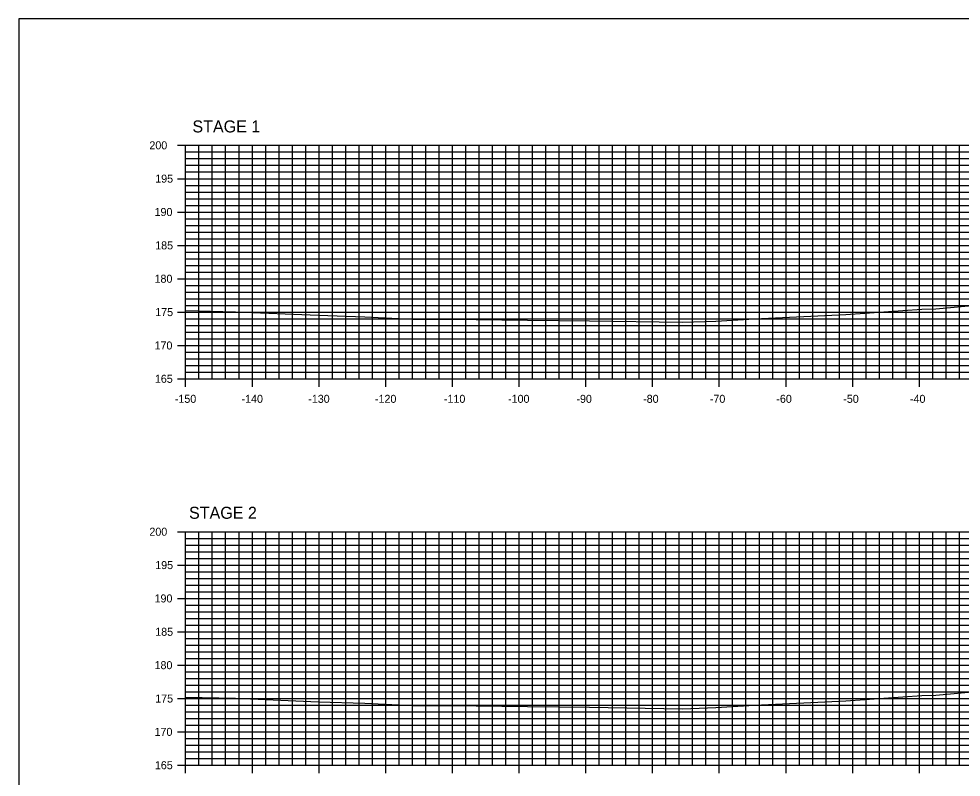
# Model space of a CAD drawing. Extents: x 1405440 to 1409538, y 1842123 to 1843178.
# Drawn here: x 1408707.6 to 1408848.9, y 1842829.8 to 1842943.5 of the extents above; entities that cross this region are included whole.
import ezdxf

# ---------------------------------------------------------------- set-up
doc = ezdxf.new("R2010")
doc.units = 0
for name, color, linetype in [('R_Axis', 7, 'Continuous'), ('R_Axis Annot', 7, 'Continuous'), ('R_Exist Surface', 7, 'Continuous'), ('R_Grid_Minor', 7, 'Continuous'), ('R_Grid_Sta', 7, 'Continuous'), ('R_Grid_Tick', 7, 'Continuous')]:
    doc.layers.add(name, color=color, linetype=linetype)

msp = doc.modelspace()

# ---------------------------------------------------------------- linework, layer by layer
for p, q in [((1408732.62, 1842924.51), (1409032.62, 1842924.51)), ((1408732.62, 1842889.51), (1408732.62, 1842924.51)), ((1408742.62, 1842889.51), (1408742.62, 1842924.51)), ((1408752.62, 1842889.51), (1408752.62, 1842924.51)), ((1408762.62, 1842889.51), (1408762.62, 1842924.51)), ((1408772.62, 1842889.51), (1408772.62, 1842924.51)), ((1408782.62, 1842889.51), (1408782.62, 1842924.51)), ((1408792.62, 1842889.51), (1408792.62, 1842924.51)), ((1408802.62, 1842889.51), (1408802.62, 1842924.51)), ((1408812.62, 1842889.51), (1408812.62, 1842924.51)), ((1408822.62, 1842889.51), (1408822.62, 1842924.51)), ((1408832.62, 1842889.51), (1408832.62, 1842924.51)), ((1408842.62, 1842889.51), (1408842.62, 1842924.51)), ((1408732.62, 1842919.51), (1409032.62, 1842919.51)), ((1408732.62, 1842914.51), (1409032.62, 1842914.51)), ((1408732.62, 1842909.51), (1409032.62, 1842909.51)), ((1408732.62, 1842904.51), (1409032.62, 1842904.51)), ((1408732.62, 1842899.51), (1409032.62, 1842899.51)), ((1408732.62, 1842894.51), (1409032.62, 1842894.51)), ((1408732.62, 1842889.51), (1409032.62, 1842889.51)), ((1408732.62, 1842889.51), (1409032.62, 1842889.51)), ((1408732.62, 1842866.59), (1409032.62, 1842866.59)), ((1408732.62, 1842831.59), (1408732.62, 1842866.59)), ((1408742.62, 1842831.59), (1408742.62, 1842866.59)), ((1408752.62, 1842831.59), (1408752.62, 1842866.59)), ((1408762.62, 1842831.59), (1408762.62, 1842866.59)), ((1408772.62, 1842831.59), (1408772.62, 1842866.59)), ((1408782.62, 1842831.59), (1408782.62, 1842866.59)), ((1408792.62, 1842831.59), (1408792.62, 1842866.59)), ((1408802.62, 1842831.59), (1408802.62, 1842866.59)), ((1408812.62, 1842831.59), (1408812.62, 1842866.59)), ((1408822.62, 1842831.59), (1408822.62, 1842866.59)), ((1408832.62, 1842831.59), (1408832.62, 1842866.59)), ((1408842.62, 1842831.59), (1408842.62, 1842866.59)), ((1408732.62, 1842861.59), (1409032.62, 1842861.59)), ((1408732.62, 1842856.59), (1409032.62, 1842856.59)), ((1408732.62, 1842851.59), (1409032.62, 1842851.59)), ((1408732.62, 1842846.59), (1409032.62, 1842846.59)), ((1408732.62, 1842841.59), (1409032.62, 1842841.59)), ((1408732.62, 1842836.59), (1409032.62, 1842836.59)), ((1408732.62, 1842831.59), (1409032.62, 1842831.59)), ((1408732.62, 1842831.59), (1409032.62, 1842831.59))]:
    msp.add_line(p, q)
msp.add_lwpolyline([(1408707.62, 1842723.47), (1409047.62, 1842723.47), (1409047.62, 1842943.47), (1408707.62, 1842943.47)], close=True)
at = {"layer": 'R_Axis'}
for p, q in [((1408732.62, 1842889.51), (1408732.62, 1842924.51)), ((1408732.62, 1842831.59), (1408732.62, 1842866.59))]:
    msp.add_line(p, q, dxfattribs=at)
at = {"layer": 'R_Exist Surface'}
for points in [[(1408732.62, 1842899.73), (1408740.12, 1842899.55), (1408752.53, 1842899.03), (1408759.46, 1842898.81), (1408766.51, 1842898.45), (1408776.19, 1842898.39), (1408783.89, 1842898.29), (1408793.18, 1842898.22), (1408807.12, 1842897.98), (1408812.08, 1842898.16), (1408817.89, 1842898.49), (1408831.59, 1842899.15), (1408842.97, 1842899.94), (1408842.98, 1842899.94), (1408845.09, 1842900.01), (1408851.63, 1842900.62)], [(1408732.62, 1842841.81), (1408740.12, 1842841.63), (1408752.53, 1842841.11), (1408759.46, 1842840.89), (1408766.51, 1842840.53), (1408776.19, 1842840.47), (1408783.89, 1842840.37), (1408793.18, 1842840.3), (1408807.12, 1842840.06), (1408812.08, 1842840.24), (1408817.89, 1842840.57), (1408831.59, 1842841.23), (1408842.97, 1842842.02), (1408842.98, 1842842.02), (1408845.09, 1842842.1), (1408851.63, 1842842.71)]]:
    msp.add_lwpolyline(points, dxfattribs=at)
at = {"layer": 'R_Grid_Minor'}
for p, q in [((1408732.62, 1842889.51), (1408732.62, 1842924.51)), ((1408734.62, 1842889.51), (1408734.62, 1842924.51)), ((1408736.62, 1842889.51), (1408736.62, 1842924.51)), ((1408738.62, 1842889.51), (1408738.62, 1842924.51)), ((1408740.62, 1842889.51), (1408740.62, 1842924.51)), ((1408744.62, 1842889.51), (1408744.62, 1842924.51)), ((1408746.62, 1842889.51), (1408746.62, 1842924.51)), ((1408748.62, 1842889.51), (1408748.62, 1842924.51)), ((1408750.62, 1842889.51), (1408750.62, 1842924.51)), ((1408754.62, 1842889.51), (1408754.62, 1842924.51)), ((1408756.62, 1842889.51), (1408756.62, 1842924.51)), ((1408758.62, 1842889.51), (1408758.62, 1842924.51)), ((1408760.62, 1842889.51), (1408760.62, 1842924.51)), ((1408764.62, 1842889.51), (1408764.62, 1842924.51)), ((1408766.62, 1842889.51), (1408766.62, 1842924.51)), ((1408768.62, 1842889.51), (1408768.62, 1842924.51)), ((1408770.62, 1842889.51), (1408770.62, 1842924.51)), ((1408774.62, 1842889.51), (1408774.62, 1842924.51)), ((1408776.62, 1842889.51), (1408776.62, 1842924.51)), ((1408778.62, 1842889.51), (1408778.62, 1842924.51)), ((1408780.62, 1842889.51), (1408780.62, 1842924.51)), ((1408784.62, 1842889.51), (1408784.62, 1842924.51)), ((1408786.62, 1842889.51), (1408786.62, 1842924.51)), ((1408788.62, 1842889.51), (1408788.62, 1842924.51)), ((1408790.62, 1842889.51), (1408790.62, 1842924.51)), ((1408794.62, 1842889.51), (1408794.62, 1842924.51)), ((1408796.62, 1842889.51), (1408796.62, 1842924.51)), ((1408798.62, 1842889.51), (1408798.62, 1842924.51)), ((1408800.62, 1842889.51), (1408800.62, 1842924.51)), ((1408804.62, 1842889.51), (1408804.62, 1842924.51)), ((1408806.62, 1842889.51), (1408806.62, 1842924.51)), ((1408808.62, 1842889.51), (1408808.62, 1842924.51)), ((1408810.62, 1842889.51), (1408810.62, 1842924.51)), ((1408814.62, 1842889.51), (1408814.62, 1842924.51)), ((1408816.62, 1842889.51), (1408816.62, 1842924.51)), ((1408818.62, 1842889.51), (1408818.62, 1842924.51)), ((1408820.62, 1842889.51), (1408820.62, 1842924.51)), ((1408824.62, 1842889.51), (1408824.62, 1842924.51)), ((1408826.62, 1842889.51), (1408826.62, 1842924.51)), ((1408828.62, 1842889.51), (1408828.62, 1842924.51)), ((1408830.62, 1842889.51), (1408830.62, 1842924.51)), ((1408834.62, 1842889.51), (1408834.62, 1842924.51)), ((1408836.62, 1842889.51), (1408836.62, 1842924.51)), ((1408838.62, 1842889.51), (1408838.62, 1842924.51)), ((1408840.62, 1842889.51), (1408840.62, 1842924.51)), ((1408844.62, 1842889.51), (1408844.62, 1842924.51)), ((1408846.62, 1842889.51), (1408846.62, 1842924.51)), ((1408848.62, 1842889.51), (1408848.62, 1842924.51)), ((1408732.62, 1842923.51), (1409032.62, 1842923.51)), ((1408732.62, 1842922.51), (1409032.62, 1842922.51)), ((1408732.62, 1842921.51), (1409032.62, 1842921.51)), ((1408732.62, 1842920.51), (1409032.62, 1842920.51)), ((1408732.62, 1842918.51), (1409032.62, 1842918.51)), ((1408732.62, 1842917.51), (1409032.62, 1842917.51)), ((1408732.62, 1842916.51), (1409032.62, 1842916.51)), ((1408732.62, 1842915.51), (1409032.62, 1842915.51)), ((1408732.62, 1842913.51), (1409032.62, 1842913.51)), ((1408732.62, 1842912.51), (1409032.62, 1842912.51)), ((1408732.62, 1842911.51), (1409032.62, 1842911.51)), ((1408732.62, 1842910.51), (1409032.62, 1842910.51)), ((1408732.62, 1842908.51), (1409032.62, 1842908.51)), ((1408732.62, 1842907.51), (1409032.62, 1842907.51)), ((1408732.62, 1842906.51), (1409032.62, 1842906.51)), ((1408732.62, 1842905.51), (1409032.62, 1842905.51)), ((1408732.62, 1842903.51), (1409032.62, 1842903.51)), ((1408732.62, 1842902.51), (1409032.62, 1842902.51)), ((1408732.62, 1842901.51), (1409032.62, 1842901.51)), ((1408732.62, 1842900.51), (1409032.62, 1842900.51)), ((1408732.62, 1842898.51), (1409032.62, 1842898.51)), ((1408732.62, 1842897.51), (1409032.62, 1842897.51)), ((1408732.62, 1842896.51), (1409032.62, 1842896.51)), ((1408732.62, 1842895.51), (1409032.62, 1842895.51)), ((1408732.62, 1842893.51), (1409032.62, 1842893.51)), ((1408732.62, 1842892.51), (1409032.62, 1842892.51)), ((1408732.62, 1842891.51), (1409032.62, 1842891.51)), ((1408732.62, 1842890.51), (1409032.62, 1842890.51)), ((1408732.62, 1842831.59), (1408732.62, 1842866.59)), ((1408734.62, 1842831.59), (1408734.62, 1842866.59)), ((1408736.62, 1842831.59), (1408736.62, 1842866.59)), ((1408738.62, 1842831.59), (1408738.62, 1842866.59)), ((1408740.62, 1842831.59), (1408740.62, 1842866.59)), ((1408744.62, 1842831.59), (1408744.62, 1842866.59)), ((1408746.62, 1842831.59), (1408746.62, 1842866.59)), ((1408748.62, 1842831.59), (1408748.62, 1842866.59)), ((1408750.62, 1842831.59), (1408750.62, 1842866.59)), ((1408754.62, 1842831.59), (1408754.62, 1842866.59)), ((1408756.62, 1842831.59), (1408756.62, 1842866.59)), ((1408758.62, 1842831.59), (1408758.62, 1842866.59)), ((1408760.62, 1842831.59), (1408760.62, 1842866.59)), ((1408764.62, 1842831.59), (1408764.62, 1842866.59)), ((1408766.62, 1842831.59), (1408766.62, 1842866.59)), ((1408768.62, 1842831.59), (1408768.62, 1842866.59)), ((1408770.62, 1842831.59), (1408770.62, 1842866.59)), ((1408774.62, 1842831.59), (1408774.62, 1842866.59)), ((1408776.62, 1842831.59), (1408776.62, 1842866.59)), ((1408778.62, 1842831.59), (1408778.62, 1842866.59)), ((1408780.62, 1842831.59), (1408780.62, 1842866.59)), ((1408784.62, 1842831.59), (1408784.62, 1842866.59)), ((1408786.62, 1842831.59), (1408786.62, 1842866.59)), ((1408788.62, 1842831.59), (1408788.62, 1842866.59)), ((1408790.62, 1842831.59), (1408790.62, 1842866.59)), ((1408794.62, 1842831.59), (1408794.62, 1842866.59)), ((1408796.62, 1842831.59), (1408796.62, 1842866.59)), ((1408798.62, 1842831.59), (1408798.62, 1842866.59)), ((1408800.62, 1842831.59), (1408800.62, 1842866.59)), ((1408804.62, 1842831.59), (1408804.62, 1842866.59)), ((1408806.62, 1842831.59), (1408806.62, 1842866.59)), ((1408808.62, 1842831.59), (1408808.62, 1842866.59)), ((1408810.62, 1842831.59), (1408810.62, 1842866.59)), ((1408814.62, 1842831.59), (1408814.62, 1842866.59)), ((1408816.62, 1842831.59), (1408816.62, 1842866.59)), ((1408818.62, 1842831.59), (1408818.62, 1842866.59)), ((1408820.62, 1842831.59), (1408820.62, 1842866.59)), ((1408824.62, 1842831.59), (1408824.62, 1842866.59)), ((1408826.62, 1842831.59), (1408826.62, 1842866.59)), ((1408828.62, 1842831.59), (1408828.62, 1842866.59)), ((1408830.62, 1842831.59), (1408830.62, 1842866.59)), ((1408834.62, 1842831.59), (1408834.62, 1842866.59)), ((1408836.62, 1842831.59), (1408836.62, 1842866.59)), ((1408838.62, 1842831.59), (1408838.62, 1842866.59)), ((1408840.62, 1842831.59), (1408840.62, 1842866.59)), ((1408844.62, 1842831.59), (1408844.62, 1842866.59)), ((1408846.62, 1842831.59), (1408846.62, 1842866.59)), ((1408848.62, 1842831.59), (1408848.62, 1842866.59)), ((1408732.62, 1842865.59), (1409032.62, 1842865.59)), ((1408732.62, 1842864.59), (1409032.62, 1842864.59)), ((1408732.62, 1842863.59), (1409032.62, 1842863.59)), ((1408732.62, 1842862.59), (1409032.62, 1842862.59)), ((1408732.62, 1842860.59), (1409032.62, 1842860.59)), ((1408732.62, 1842859.59), (1409032.62, 1842859.59)), ((1408732.62, 1842858.59), (1409032.62, 1842858.59)), ((1408732.62, 1842857.59), (1409032.62, 1842857.59)), ((1408732.62, 1842855.59), (1409032.62, 1842855.59)), ((1408732.62, 1842854.59), (1409032.62, 1842854.59)), ((1408732.62, 1842853.59), (1409032.62, 1842853.59)), ((1408732.62, 1842852.59), (1409032.62, 1842852.59)), ((1408732.62, 1842850.59), (1409032.62, 1842850.59)), ((1408732.62, 1842849.59), (1409032.62, 1842849.59)), ((1408732.62, 1842848.59), (1409032.62, 1842848.59)), ((1408732.62, 1842847.59), (1409032.62, 1842847.59)), ((1408732.62, 1842845.59), (1409032.62, 1842845.59)), ((1408732.62, 1842844.59), (1409032.62, 1842844.59)), ((1408732.62, 1842843.59), (1409032.62, 1842843.59)), ((1408732.62, 1842842.59), (1409032.62, 1842842.59)), ((1408732.62, 1842840.59), (1409032.62, 1842840.59)), ((1408732.62, 1842839.59), (1409032.62, 1842839.59)), ((1408732.62, 1842838.59), (1409032.62, 1842838.59)), ((1408732.62, 1842837.59), (1409032.62, 1842837.59)), ((1408732.62, 1842835.59), (1409032.62, 1842835.59)), ((1408732.62, 1842834.59), (1409032.62, 1842834.59)), ((1408732.62, 1842833.59), (1409032.62, 1842833.59)), ((1408732.62, 1842832.59), (1409032.62, 1842832.59))]:
    msp.add_line(p, q, dxfattribs=at)
at = {"layer": 'R_Grid_Tick'}
for p, q in [((1408731.42, 1842924.51), (1408733.82, 1842924.51)), ((1408732.62, 1842923.51), (1408733.22, 1842923.51)), ((1408732.62, 1842922.51), (1408733.22, 1842922.51)), ((1408732.62, 1842921.51), (1408733.22, 1842921.51)), ((1408732.62, 1842920.51), (1408733.22, 1842920.51)), ((1408731.42, 1842919.51), (1408733.82, 1842919.51)), ((1408732.62, 1842918.51), (1408733.22, 1842918.51)), ((1408732.62, 1842917.51), (1408733.22, 1842917.51)), ((1408732.62, 1842916.51), (1408733.22, 1842916.51)), ((1408731.42, 1842914.51), (1408733.82, 1842914.51)), ((1408732.62, 1842915.51), (1408733.22, 1842915.51)), ((1408732.62, 1842913.51), (1408733.22, 1842913.51)), ((1408732.62, 1842912.51), (1408733.22, 1842912.51)), ((1408732.62, 1842911.51), (1408733.22, 1842911.51)), ((1408732.62, 1842910.51), (1408733.22, 1842910.51)), ((1408731.42, 1842909.51), (1408733.82, 1842909.51)), ((1408732.62, 1842908.51), (1408733.22, 1842908.51)), ((1408732.62, 1842907.51), (1408733.22, 1842907.51)), ((1408732.62, 1842906.51), (1408733.22, 1842906.51)), ((1408731.42, 1842904.51), (1408733.82, 1842904.51)), ((1408732.62, 1842905.51), (1408733.22, 1842905.51)), ((1408732.62, 1842903.51), (1408733.22, 1842903.51)), ((1408732.62, 1842902.51), (1408733.22, 1842902.51)), ((1408732.62, 1842901.51), (1408733.22, 1842901.51)), ((1408732.62, 1842900.51), (1408733.22, 1842900.51)), ((1408731.42, 1842899.51), (1408733.82, 1842899.51)), ((1408732.62, 1842898.51), (1408733.22, 1842898.51)), ((1408732.62, 1842897.51), (1408733.22, 1842897.51)), ((1408732.62, 1842896.51), (1408733.22, 1842896.51)), ((1408732.62, 1842895.51), (1408733.22, 1842895.51)), ((1408731.42, 1842894.51), (1408733.82, 1842894.51)), ((1408732.62, 1842893.51), (1408733.22, 1842893.51)), ((1408732.62, 1842892.51), (1408733.22, 1842892.51)), ((1408732.62, 1842891.51), (1408733.22, 1842891.51)), ((1408732.62, 1842888.31), (1408732.62, 1842890.71)), ((1408732.62, 1842890.51), (1408733.22, 1842890.51)), ((1408742.62, 1842888.31), (1408742.62, 1842890.71)), ((1408752.62, 1842888.31), (1408752.62, 1842890.71)), ((1408762.62, 1842888.31), (1408762.62, 1842890.71)), ((1408772.62, 1842888.31), (1408772.62, 1842890.71)), ((1408782.62, 1842888.31), (1408782.62, 1842890.71)), ((1408792.62, 1842888.31), (1408792.62, 1842890.71)), ((1408802.62, 1842888.31), (1408802.62, 1842890.71)), ((1408812.62, 1842888.31), (1408812.62, 1842890.71)), ((1408822.62, 1842888.31), (1408822.62, 1842890.71)), ((1408832.62, 1842888.31), (1408832.62, 1842890.71)), ((1408842.62, 1842888.31), (1408842.62, 1842890.71)), ((1408731.42, 1842889.51), (1408733.82, 1842889.51)), ((1408732.62, 1842889.51), (1408732.62, 1842890.11)), ((1408734.62, 1842889.51), (1408734.62, 1842890.11)), ((1408736.62, 1842889.51), (1408736.62, 1842890.11)), ((1408738.62, 1842889.51), (1408738.62, 1842890.11)), ((1408740.62, 1842889.51), (1408740.62, 1842890.11)), ((1408744.62, 1842889.51), (1408744.62, 1842890.11)), ((1408746.62, 1842889.51), (1408746.62, 1842890.11)), ((1408748.62, 1842889.51), (1408748.62, 1842890.11)), ((1408750.62, 1842889.51), (1408750.62, 1842890.11)), ((1408754.62, 1842889.51), (1408754.62, 1842890.11)), ((1408756.62, 1842889.51), (1408756.62, 1842890.11)), ((1408758.62, 1842889.51), (1408758.62, 1842890.11)), ((1408760.62, 1842889.51), (1408760.62, 1842890.11)), ((1408764.62, 1842889.51), (1408764.62, 1842890.11)), ((1408766.62, 1842889.51), (1408766.62, 1842890.11)), ((1408768.62, 1842889.51), (1408768.62, 1842890.11)), ((1408770.62, 1842889.51), (1408770.62, 1842890.11)), ((1408774.62, 1842889.51), (1408774.62, 1842890.11)), ((1408776.62, 1842889.51), (1408776.62, 1842890.11)), ((1408778.62, 1842889.51), (1408778.62, 1842890.11)), ((1408780.62, 1842889.51), (1408780.62, 1842890.11)), ((1408784.62, 1842889.51), (1408784.62, 1842890.11)), ((1408786.62, 1842889.51), (1408786.62, 1842890.11)), ((1408788.62, 1842889.51), (1408788.62, 1842890.11)), ((1408790.62, 1842889.51), (1408790.62, 1842890.11)), ((1408794.62, 1842889.51), (1408794.62, 1842890.11)), ((1408796.62, 1842889.51), (1408796.62, 1842890.11)), ((1408798.62, 1842889.51), (1408798.62, 1842890.11)), ((1408800.62, 1842889.51), (1408800.62, 1842890.11)), ((1408804.62, 1842889.51), (1408804.62, 1842890.11)), ((1408806.62, 1842889.51), (1408806.62, 1842890.11)), ((1408808.62, 1842889.51), (1408808.62, 1842890.11)), ((1408810.62, 1842889.51), (1408810.62, 1842890.11)), ((1408814.62, 1842889.51), (1408814.62, 1842890.11)), ((1408816.62, 1842889.51), (1408816.62, 1842890.11)), ((1408818.62, 1842889.51), (1408818.62, 1842890.11)), ((1408820.62, 1842889.51), (1408820.62, 1842890.11)), ((1408824.62, 1842889.51), (1408824.62, 1842890.11)), ((1408826.62, 1842889.51), (1408826.62, 1842890.11)), ((1408828.62, 1842889.51), (1408828.62, 1842890.11)), ((1408830.62, 1842889.51), (1408830.62, 1842890.11)), ((1408834.62, 1842889.51), (1408834.62, 1842890.11)), ((1408836.62, 1842889.51), (1408836.62, 1842890.11)), ((1408838.62, 1842889.51), (1408838.62, 1842890.11)), ((1408840.62, 1842889.51), (1408840.62, 1842890.11)), ((1408844.62, 1842889.51), (1408844.62, 1842890.11)), ((1408846.62, 1842889.51), (1408846.62, 1842890.11)), ((1408848.62, 1842889.51), (1408848.62, 1842890.11)), ((1408731.42, 1842866.59), (1408733.82, 1842866.59)), ((1408732.62, 1842865.59), (1408733.22, 1842865.59)), ((1408732.62, 1842864.59), (1408733.22, 1842864.59)), ((1408732.62, 1842863.59), (1408733.22, 1842863.59)), ((1408732.62, 1842862.59), (1408733.22, 1842862.59)), ((1408731.42, 1842861.59), (1408733.82, 1842861.59)), ((1408732.62, 1842860.59), (1408733.22, 1842860.59)), ((1408732.62, 1842859.59), (1408733.22, 1842859.59)), ((1408732.62, 1842858.59), (1408733.22, 1842858.59)), ((1408731.42, 1842856.59), (1408733.82, 1842856.59)), ((1408732.62, 1842857.59), (1408733.22, 1842857.59)), ((1408732.62, 1842855.59), (1408733.22, 1842855.59)), ((1408732.62, 1842854.59), (1408733.22, 1842854.59)), ((1408732.62, 1842853.59), (1408733.22, 1842853.59)), ((1408732.62, 1842852.59), (1408733.22, 1842852.59)), ((1408731.42, 1842851.59), (1408733.82, 1842851.59)), ((1408732.62, 1842850.59), (1408733.22, 1842850.59)), ((1408732.62, 1842849.59), (1408733.22, 1842849.59)), ((1408732.62, 1842848.59), (1408733.22, 1842848.59)), ((1408731.42, 1842846.59), (1408733.82, 1842846.59)), ((1408732.62, 1842847.59), (1408733.22, 1842847.59)), ((1408732.62, 1842845.59), (1408733.22, 1842845.59)), ((1408732.62, 1842844.59), (1408733.22, 1842844.59)), ((1408732.62, 1842843.59), (1408733.22, 1842843.59)), ((1408732.62, 1842842.59), (1408733.22, 1842842.59)), ((1408731.42, 1842841.59), (1408733.82, 1842841.59)), ((1408732.62, 1842840.59), (1408733.22, 1842840.59)), ((1408732.62, 1842839.59), (1408733.22, 1842839.59)), ((1408732.62, 1842838.59), (1408733.22, 1842838.59)), ((1408732.62, 1842837.59), (1408733.22, 1842837.59)), ((1408731.42, 1842836.59), (1408733.82, 1842836.59)), ((1408732.62, 1842835.59), (1408733.22, 1842835.59)), ((1408732.62, 1842834.59), (1408733.22, 1842834.59)), ((1408732.62, 1842833.59), (1408733.22, 1842833.59)), ((1408732.62, 1842830.39), (1408732.62, 1842832.79)), ((1408732.62, 1842832.59), (1408733.22, 1842832.59)), ((1408742.62, 1842830.39), (1408742.62, 1842832.79)), ((1408752.62, 1842830.39), (1408752.62, 1842832.79)), ((1408762.62, 1842830.39), (1408762.62, 1842832.79)), ((1408772.62, 1842830.39), (1408772.62, 1842832.79)), ((1408782.62, 1842830.39), (1408782.62, 1842832.79)), ((1408792.62, 1842830.39), (1408792.62, 1842832.79)), ((1408802.62, 1842830.39), (1408802.62, 1842832.79)), ((1408812.62, 1842830.39), (1408812.62, 1842832.79)), ((1408822.62, 1842830.39), (1408822.62, 1842832.79)), ((1408832.62, 1842830.39), (1408832.62, 1842832.79)), ((1408842.62, 1842830.39), (1408842.62, 1842832.79)), ((1408731.42, 1842831.59), (1408733.82, 1842831.59)), ((1408732.62, 1842831.59), (1408732.62, 1842832.19)), ((1408734.62, 1842831.59), (1408734.62, 1842832.19)), ((1408736.62, 1842831.59), (1408736.62, 1842832.19)), ((1408738.62, 1842831.59), (1408738.62, 1842832.19)), ((1408740.62, 1842831.59), (1408740.62, 1842832.19)), ((1408744.62, 1842831.59), (1408744.62, 1842832.19)), ((1408746.62, 1842831.59), (1408746.62, 1842832.19)), ((1408748.62, 1842831.59), (1408748.62, 1842832.19)), ((1408750.62, 1842831.59), (1408750.62, 1842832.19)), ((1408754.62, 1842831.59), (1408754.62, 1842832.19)), ((1408756.62, 1842831.59), (1408756.62, 1842832.19)), ((1408758.62, 1842831.59), (1408758.62, 1842832.19)), ((1408760.62, 1842831.59), (1408760.62, 1842832.19)), ((1408764.62, 1842831.59), (1408764.62, 1842832.19)), ((1408766.62, 1842831.59), (1408766.62, 1842832.19)), ((1408768.62, 1842831.59), (1408768.62, 1842832.19)), ((1408770.62, 1842831.59), (1408770.62, 1842832.19)), ((1408774.62, 1842831.59), (1408774.62, 1842832.19)), ((1408776.62, 1842831.59), (1408776.62, 1842832.19)), ((1408778.62, 1842831.59), (1408778.62, 1842832.19)), ((1408780.62, 1842831.59), (1408780.62, 1842832.19)), ((1408784.62, 1842831.59), (1408784.62, 1842832.19)), ((1408786.62, 1842831.59), (1408786.62, 1842832.19)), ((1408788.62, 1842831.59), (1408788.62, 1842832.19)), ((1408790.62, 1842831.59), (1408790.62, 1842832.19)), ((1408794.62, 1842831.59), (1408794.62, 1842832.19)), ((1408796.62, 1842831.59), (1408796.62, 1842832.19)), ((1408798.62, 1842831.59), (1408798.62, 1842832.19)), ((1408800.62, 1842831.59), (1408800.62, 1842832.19)), ((1408804.62, 1842831.59), (1408804.62, 1842832.19)), ((1408806.62, 1842831.59), (1408806.62, 1842832.19)), ((1408808.62, 1842831.59), (1408808.62, 1842832.19)), ((1408810.62, 1842831.59), (1408810.62, 1842832.19)), ((1408814.62, 1842831.59), (1408814.62, 1842832.19)), ((1408816.62, 1842831.59), (1408816.62, 1842832.19)), ((1408818.62, 1842831.59), (1408818.62, 1842832.19)), ((1408820.62, 1842831.59), (1408820.62, 1842832.19)), ((1408824.62, 1842831.59), (1408824.62, 1842832.19)), ((1408826.62, 1842831.59), (1408826.62, 1842832.19)), ((1408828.62, 1842831.59), (1408828.62, 1842832.19)), ((1408830.62, 1842831.59), (1408830.62, 1842832.19)), ((1408834.62, 1842831.59), (1408834.62, 1842832.19)), ((1408836.62, 1842831.59), (1408836.62, 1842832.19)), ((1408838.62, 1842831.59), (1408838.62, 1842832.19)), ((1408840.62, 1842831.59), (1408840.62, 1842832.19)), ((1408844.62, 1842831.59), (1408844.62, 1842832.19)), ((1408846.62, 1842831.59), (1408846.62, 1842832.19)), ((1408848.62, 1842831.59), (1408848.62, 1842832.19))]:
    msp.add_line(p, q, dxfattribs=at)

# ---------------------------------------------------------------- texts
at = {"layer": 'R_Axis'}
for p in [(1408732.62, 1842889.51), (1408732.62, 1842831.59)]:
    msp.add_text('-', height=0.0001, dxfattribs=at).set_placement(p)
at = {"layer": 'R_Axis Annot'}
for s, p in [('200', (1408727.19, 1842923.91)), ('195', (1408728.06, 1842918.91)), ('190', (1408727.96, 1842913.91)), ('185', (1408728.06, 1842908.91)), ('180', (1408727.96, 1842903.91)), ('175', (1408728.06, 1842898.91)), ('170', (1408727.96, 1842893.91)), ('165', (1408728.01, 1842888.91)), ('-150', (1408731, 1842885.91)), ('-140', (1408741, 1842885.91)), ('-130', (1408751, 1842885.91)), ('-120', (1408761, 1842885.91)), ('-110', (1408771.34, 1842885.91)), ('-100', (1408780.95, 1842885.91)), ('-90', (1408791.2, 1842885.91)), ('-80', (1408801.2, 1842885.91)), ('-70', (1408811.2, 1842885.91)), ('-60', (1408821.17, 1842885.91)), ('-50', (1408831.2, 1842885.91)), ('-40', (1408841.2, 1842885.91)), ('200', (1408727.19, 1842865.99)), ('195', (1408728.06, 1842860.99)), ('190', (1408727.96, 1842855.99)), ('185', (1408728.06, 1842850.99)), ('180', (1408727.96, 1842845.99)), ('175', (1408728.06, 1842840.99)), ('170', (1408727.96, 1842835.99)), ('165', (1408728.01, 1842830.99))]:
    msp.add_text(s, height=1.2, dxfattribs=at).set_placement(p)
at = {"layer": 'R_Grid_Sta'}
for s, p in [('STAGE 1', (1408733.64, 1842926.44)), ('STAGE 2', (1408733.13, 1842868.53))]:
    msp.add_text(s, height=1.8, dxfattribs=at).set_placement(p)

doc.saveas('drawing.dxf')
